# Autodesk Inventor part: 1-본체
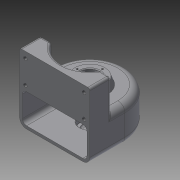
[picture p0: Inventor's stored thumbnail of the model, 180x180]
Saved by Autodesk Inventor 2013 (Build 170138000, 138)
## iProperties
Created: 2015-02
Part Number: 1-본체
Material: 일반
Document SubType Name: Modeling
Designer: Administrator
Density: 1 g/cm^3
Author: Administrator
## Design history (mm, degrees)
sketch "스케치1"
  geometry: L1 (-50, 0)-(-50, -50); L2 (50, 0)-(50, -50); L3 (-50, -50)-(50, -50); A1 r 50 centre (0, 0) between (-50, 0) and (50, 0); 1 further point
  constraints: 6 end point, 2 point on circle, 2 tangent, 1 centre point, 1 coincident, 1 parallel, 1 perpendicular, 1 vertical
  dimensions: "d0" = 100 diameter of A1; "d6" = 50 distance from line of point (0, 0) L3
extrude "돌출1" new body sketch "스케치1" distance "d4" = 50; taper "d5" = 0 deg
node "작업 평면1"
sketch "스케치3"
  geometry: L1 (-50, 0)-(-50, -50) reference; L2 (-50, -50)-(50, -50) reference; L3 (50, -50)-(50, 0) reference; L4 (-50, -50)-(50, -50); L5 (50, -50)-(50, -20); L6 (-50, -20)-(-50, -50); L7 (50, -20)-(34.641, -20); L8 (-34.641, -20)-(-50, -20); A1 r 40 centre (0, 0) between (-34.641, -20) and (34.641, -20); 1 further point
  constraints: 10 end point, 3 parallel, 2 point on circle, 1 centre point, 1 coincident, 1 horizontal, 1 perpendicular, 1 point on line
  dimensions: "d8" = 30 distance of L6.start L1.end; "d9" = 80 diameter of A1; "d10" = 20 distance from line of point (0, 0) L7
extrude "돌출2" join sketch "스케치3" stored distance "d11" = 50; taper "d12" = 0 deg
sketch "스케치4"
  geometry: L1 (50, 50)-(0, 50) reference; L2 (0, 50)-(-20, 50) reference; L3 (25, 50)-(21.36, 60); L4 (0, 195.305)-(0, 0); L5 (25, 50)-(0, 50); L6 (21.36, 60)-(0, 60); L7 (0, 60)-(0, 50); 1 further point
  constraints: 10 end point, 2 collinear, 2 perpendicular, 1 coincident, 1 midpoint, 1 point on line
  dimensions: "d13" = 110 deg angle of L1 L3; "d14" = 50 diameter of L3.start L4; "d16" = 10 vertical distance of L1.end L3.end
revolve "회전1" sketch "스케치4" stored, may be unused: angle "d17" = 90 deg
node "작업 평면2"
sketch "스케치5"
  geometry: L1 (-50, -50)-(50, -50) reference; L2 (-46, 0)-(-46, -50); L3 (-46, -50)-(46, -50); L4 (46, 0)-(46, -50); A1 r 46 centre (0, 0) between (-46, 0) and (46, 0); 1 further point
  constraints: 6 end point, 2 perpendicular, 2 point on circle, 2 point on line, 2 tangent, 1 centre point, 1 coincident
  dimensions: "d19" = 92 diameter of A1
extrude "돌출3" cut sketch "스케치5" stored distance "d21" = 42; taper "d22" = 0 deg
fillet "모깎기1" dims "d23" = 6
sketch "스케치6"
  geometry: C1 r 21.36 at (0, 0) reference; 1 further point
  constraints: 1 coincident
hole "구멍1" sketch "스케치6" at (0, 0) diameter "d24" = 20; stored, may be unused: countersink angle "d28" = 90 deg, drill point angle "d30" = 0 deg; dims "d25" = 6, "d26" = 28, "d27" = 10, "d29" = 4
sketch "스케치7"
  geometry: C1 r 20 at (0, 0); A1 r 50 centre (0, 0) between (50, 0) and (-50, 0) reference
  constraints: 1 centre point, 1 coincident
  dimensions: "d31" = 40 diameter of C1
extrude "돌출4" join sketch "스케치7" distance "d33" = 9; taper "d34" = 0 deg
sketch "스케치8"
  geometry: C1 r 14 at (0, 0); A1 r 40 centre (0, 0) between (40, 0) and (-40, 0) reference; 1 further point
  constraints: 2 coincident, 1 centre point
  dimensions: "d35" = 28 diameter of C1
hole "구멍2" sketch "스케치8" at (0, 0) diameter "d37" = 20; stored, may be unused: countersink angle "d41" = 90 deg, drill point angle "d43" = 0 deg; dims "d38" = 6, "d39" = 28, "d40" = 8, "d42" = 2
fillet "모깎기2" dims "d44" = 3
fillet "모깎기3" dims "d45" = 0.3
chamfer "모따기1" distance "d46" = 1; stored, may be unused: second distance "d47" = 2, angle "d48" = 45 deg
fillet "모깎기4" dims "d49" = 3
fillet "모깎기5" dims "d50" = 10
fillet "모깎기8" dims "d53" = 3
sketch "스케치9"
  geometry: C1 r 14 at (0, 0) reference; 1 further point
  constraints: 1 vertical alignment
  dimensions: "d54" = 18 distance of C1.centre point (0, 18)
hole "구멍3" sketch "스케치9" at (0, 18) diameter "d55" = 2.459; stored, may be unused: countersink angle "d59" = 90 deg, drill point angle "d61" = 118 deg; dims "d56" = 6, "d57" = 4, "d58" = 2, "d60" = 9
sketch "스케치10"
  geometry: L1 (0, 0)-(100, 0) reference; 5 further points
  constraints: 2 horizontal alignment, 2 vertical alignment
  dimensions: "d66" = 83.5 distance of point (91.75, -9) point (8.25, -9); "d67" = 9 distance from line of point (91.75, -9) L1; "d68" = 33 distance of point (91.75, -42) point (91.75, -9); "d69" = 41.75 horizontal distance of point (50, -95) point (8.25, -9)
hole "구멍4" sketch "스케치10" at (8.25, -9), (91.75, -9), (91.75, -42), (8.25, -42) diameter "d70" = 5.134; stored, may be unused: countersink angle "d74" = 90 deg, drill point angle "d76" = 118 deg; dims "d71" = 10, "d72" = 4, "d73" = 2, "d75" = 13
fillet "모깎기9" dims "d77" = 3
chamfer "모따기2" distance "d78" = 1; stored, may be unused: second distance "d79" = 2, angle "d80" = 45 deg
node "작업 평면3"
sketch "스케치11"
  geometry: L1 (40, 0)-(-40, 0) reference; 2 further points
  constraints: 1 vertical alignment, 1 other
  dimensions: "d82" = 25 distance from line of point (0, 25) L1
feature "엠보싱1" sketch "스케치11" dims "d0" = 100, "d6" = 50, "d83" = 0.5, "d84" = 0
fillet "모깎기10" dims "d85" = 3
node "솔리드1"
pattern_circular "원형 패턴1" dims angle "d63" = 360 deg
other parameters: "d7" = 45, "d18" = 25
